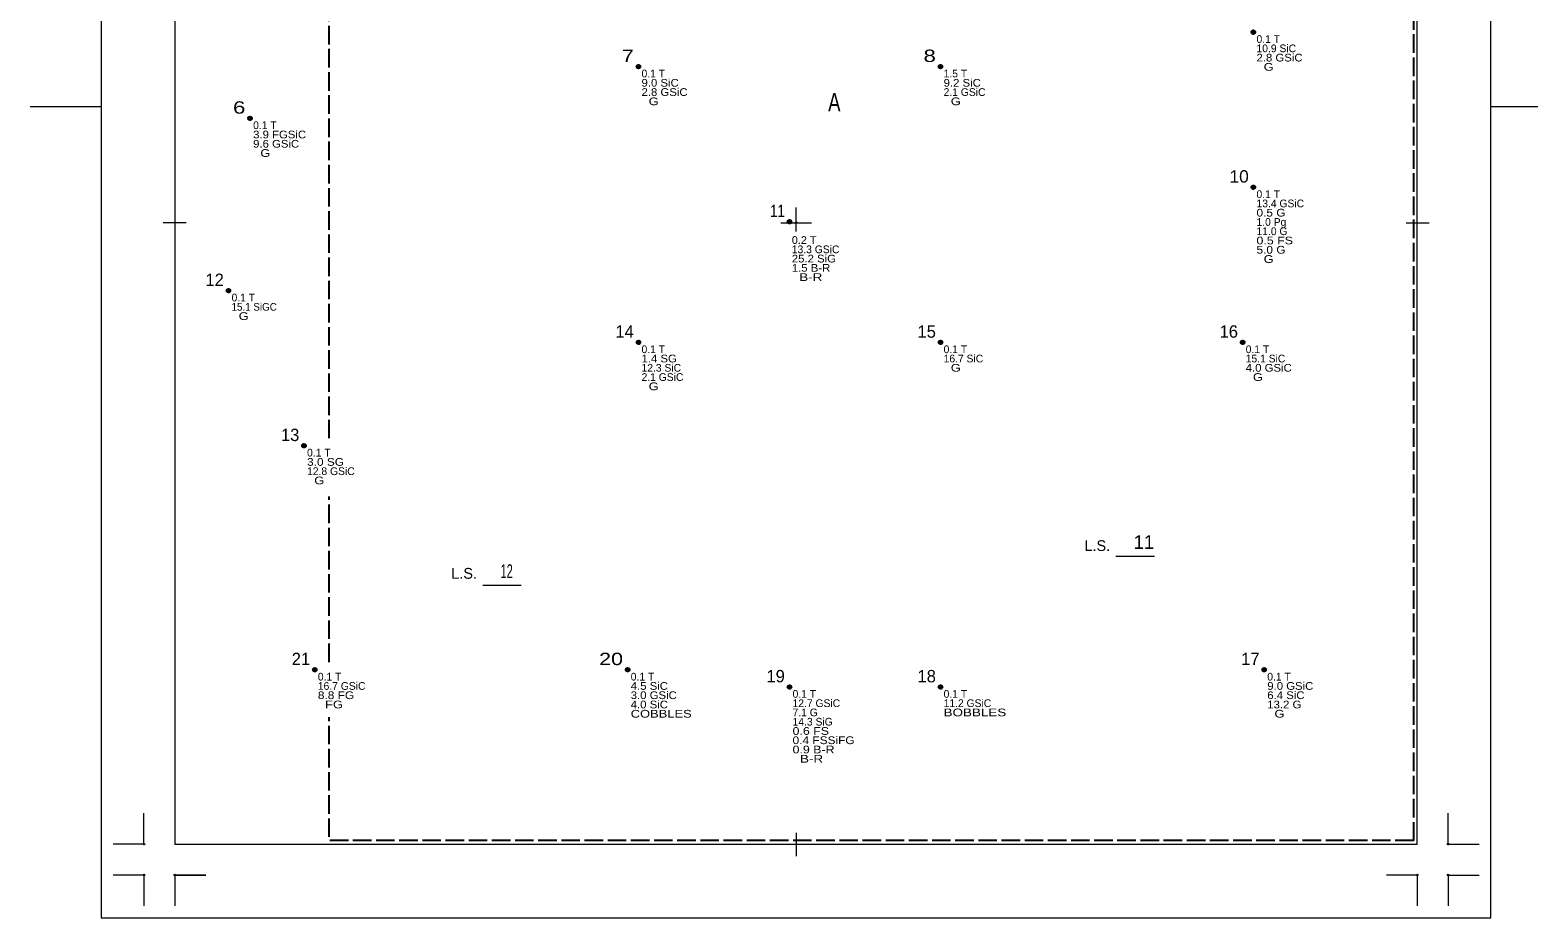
# Model space of a CAD drawing. Extents: x -496 to 480, y -450 to 700.
# Drawn here: x -496 to 480, y -450 to 125 of the extents above; entities that cross this region are included whole.
import ezdxf
from ezdxf.enums import TextEntityAlignment as Align

# ---------------------------------------------------------------- set-up
doc = ezdxf.new("R2010")
doc.units = 0
doc.header["$LTSCALE"] = 2
doc.header["$PDMODE"] = 32
doc.header["$PDSIZE"] = 1
doc.linetypes.add('LONG_DASHED', pattern=[7.5, 6, -1.5])
doc.layers.add('1', color=7, linetype='Continuous', lineweight=13)
doc.layers.add('2', color=7, linetype='Continuous', lineweight=35)

msp = doc.modelspace()

# ---------------------------------------------------------------- linework, layer by layer
at = {"layer": '1'}
for p, q in [((-402.391, 402.339), (-402.391, -402.333)), ((-450.017, 74.973), (-496.057, 74.973)), ((480.331, 74.973), (449.983, 74.973)), ((-0.017, -5.706), (-0.017, 9.973)), ((-395.017, -0.027), (-410.017, -0.027)), ((-10.017, -0.027), (9.983, -0.027)), ((394.983, -0.027), (409.983, -0.027)), ((207.114, -215.907), (232.114, -215.907)), ((-202.998, -234.618), (-177.998, -234.618)), ((-422.391, -402.333), (-422.391, -382.333)), ((422.281, -402.333), (422.281, -382.333)), ((-0.017, -395.027), (-0.017, -410.027)), ((-422.391, -402.333), (-442.391, -402.333)), ((-402.391, -402.333), (402.281, -402.333)), ((422.281, -402.333), (442.281, -402.333)), ((-422.391, -422.333), (-442.391, -422.333)), ((-422.391, -422.333), (-422.391, -442.333)), ((-402.391, -422.333), (-402.391, -442.333)), ((402.281, -422.333), (382.281, -422.333)), ((402.281, -422.333), (402.281, -442.333)), ((422.281, -422.333), (422.281, -442.333)), ((422.281, -422.333), (442.281, -422.333)), ((-450.017, -450.027), (449.983, -450.027))]:
    msp.add_line(p, q, dxfattribs=at)
for points in [[(449.983, -450.027), (449.983, 399.973), (449.983, 699.973), (-450.017, 699.973), (-450.017, 49.973), (-450.017, -450.027)], [(402.281, -402.333), (402.281, 402.339), (-402.391, 402.339)], [(-402.391, -422.333), (-382.391, -422.333), (-402.391, -422.333)]]:
    msp.add_lwpolyline(points, dxfattribs=at)
for p in [(0, 0), (0.001, -0.011), (-422.391, -402.333), (422.281, -402.333), (-422.391, -422.333), (-402.391, -422.333), (402.281, -422.333), (422.281, -422.333)]:
    msp.add_point(p, dxfattribs=at)
at = {"layer": '2', "linetype": 'LONG_DASHED', "lineweight": 25}
for p, q in [((-302.391, -139.499), (-302.391, 402.339)), ((-302.391, -284.427), (-302.391, -177.191)), ((-302.391, -397.661), (-302.391, -320.02)), ((400, -400), (-302.391, -400))]:
    msp.add_line(p, q, dxfattribs=at)
msp.add_lwpolyline([(400, -400), (400, 400), (-302.391, 400)], dxfattribs=at)
at = {"layer": '2'}
for centre in [(296.124, 123.414), (-102.135, 101.1), (93.501, 101.1), (-353.667, 67.629), (296.124, 23.001), (-4.317, 0.687), (-367.641, -43.941), (-102.135, -77.412), (93.501, -77.412), (289.137, -77.412), (-318.732, -144.354), (-311.745, -289.395), (-109.122, -289.395), (303.111, -289.395), (-4.317, -300.552), (93.501, -300.552)]:
    msp.add_circle(centre, 1, dxfattribs=at)
for points in [[(296.113, 124.301), (296.843, 123.897), (296.995, 123.048), (296.31, 122.52), (295.501, 122.751), (295.214, 123.509), (295.461, 124.071), (296.034, 124.239), (296.708, 123.745), (296.692, 123.003), (296.175, 122.745), (295.652, 122.914), (295.428, 123.56), (296.012, 124.026), (296.45, 123.492), (296.411, 123.009), (295.782, 123.144), (295.928, 123.779), (296.22, 123.228)], [(-102.146, 101.987), (-101.416, 101.583), (-101.264, 100.734), (-101.949, 100.206), (-102.758, 100.437), (-103.045, 101.195), (-102.798, 101.757), (-102.225, 101.925), (-101.551, 101.431), (-101.567, 100.689), (-102.084, 100.431), (-102.607, 100.6), (-102.831, 101.246), (-102.247, 101.712), (-101.809, 101.178), (-101.848, 100.695), (-102.477, 100.83), (-102.331, 101.465), (-102.039, 100.914)], [(93.49, 101.987), (94.22, 101.583), (94.372, 100.734), (93.687, 100.206), (92.878, 100.437), (92.591, 101.195), (92.838, 101.757), (93.411, 101.925), (94.085, 101.431), (94.069, 100.689), (93.552, 100.431), (93.029, 100.6), (92.805, 101.246), (93.389, 101.712), (93.827, 101.178), (93.788, 100.695), (93.159, 100.83), (93.305, 101.465), (93.597, 100.914)], [(-353.678, 68.516), (-352.948, 68.112), (-352.796, 67.263), (-353.481, 66.735), (-354.29, 66.966), (-354.577, 67.724), (-354.33, 68.286), (-353.757, 68.454), (-353.083, 67.96), (-353.099, 67.218), (-353.616, 66.96), (-354.139, 67.129), (-354.363, 67.775), (-353.779, 68.241), (-353.341, 67.707), (-353.38, 67.224), (-354.009, 67.359), (-353.863, 67.994), (-353.571, 67.443)], [(296.113, 23.888), (296.843, 23.484), (296.995, 22.635), (296.31, 22.107), (295.501, 22.338), (295.214, 23.096), (295.461, 23.658), (296.034, 23.826), (296.708, 23.332), (296.692, 22.59), (296.175, 22.332), (295.652, 22.501), (295.428, 23.147), (296.012, 23.613), (296.45, 23.079), (296.411, 22.596), (295.782, 22.731), (295.928, 23.366), (296.22, 22.815)], [(-4.328, 1.574), (-3.598, 1.17), (-3.446, 0.321), (-4.131, -0.207), (-4.94, 0.024), (-5.227, 0.782), (-4.98, 1.344), (-4.407, 1.512), (-3.733, 1.018), (-3.749, 0.276), (-4.266, 0.018), (-4.789, 0.187), (-5.013, 0.833), (-4.429, 1.299), (-3.991, 0.765), (-4.03, 0.282), (-4.659, 0.417), (-4.513, 1.052), (-4.221, 0.501)], [(-367.652, -43.054), (-366.922, -43.458), (-366.77, -44.307), (-367.455, -44.835), (-368.264, -44.604), (-368.551, -43.846), (-368.304, -43.284), (-367.731, -43.116), (-367.057, -43.61), (-367.073, -44.352), (-367.59, -44.61), (-368.113, -44.441), (-368.337, -43.795), (-367.753, -43.329), (-367.315, -43.863), (-367.354, -44.346), (-367.983, -44.211), (-367.837, -43.576), (-367.545, -44.127)], [(-102.146, -76.525), (-101.416, -76.929), (-101.264, -77.778), (-101.949, -78.306), (-102.758, -78.075), (-103.045, -77.317), (-102.798, -76.755), (-102.225, -76.587), (-101.551, -77.081), (-101.567, -77.823), (-102.084, -78.081), (-102.607, -77.912), (-102.831, -77.266), (-102.247, -76.8), (-101.809, -77.334), (-101.848, -77.817), (-102.477, -77.682), (-102.331, -77.047), (-102.039, -77.598)], [(93.49, -76.525), (94.22, -76.929), (94.372, -77.778), (93.687, -78.306), (92.878, -78.075), (92.591, -77.317), (92.838, -76.755), (93.411, -76.587), (94.085, -77.081), (94.069, -77.823), (93.552, -78.081), (93.029, -77.912), (92.805, -77.266), (93.389, -76.8), (93.827, -77.334), (93.788, -77.817), (93.159, -77.682), (93.305, -77.047), (93.597, -77.598)], [(289.126, -76.525), (289.856, -76.929), (290.008, -77.778), (289.323, -78.306), (288.514, -78.075), (288.227, -77.317), (288.474, -76.755), (289.047, -76.587), (289.721, -77.081), (289.705, -77.823), (289.188, -78.081), (288.665, -77.912), (288.441, -77.266), (289.025, -76.8), (289.463, -77.334), (289.424, -77.817), (288.795, -77.682), (288.941, -77.047), (289.233, -77.598)], [(-318.743, -143.467), (-318.013, -143.871), (-317.861, -144.72), (-318.546, -145.248), (-319.355, -145.017), (-319.642, -144.259), (-319.395, -143.697), (-318.822, -143.529), (-318.148, -144.023), (-318.164, -144.765), (-318.681, -145.023), (-319.204, -144.854), (-319.428, -144.208), (-318.844, -143.742), (-318.406, -144.276), (-318.445, -144.759), (-319.074, -144.624), (-318.928, -143.989), (-318.636, -144.54)], [(-311.756, -288.508), (-311.026, -288.912), (-310.874, -289.761), (-311.559, -290.289), (-312.368, -290.058), (-312.655, -289.3), (-312.408, -288.738), (-311.835, -288.57), (-311.161, -289.064), (-311.177, -289.806), (-311.694, -290.064), (-312.217, -289.895), (-312.441, -289.249), (-311.857, -288.783), (-311.419, -289.317), (-311.458, -289.8), (-312.087, -289.665), (-311.941, -289.03), (-311.649, -289.581)], [(-109.133, -288.508), (-108.403, -288.912), (-108.251, -289.761), (-108.936, -290.289), (-109.745, -290.058), (-110.032, -289.3), (-109.785, -288.738), (-109.212, -288.57), (-108.538, -289.064), (-108.554, -289.806), (-109.071, -290.064), (-109.594, -289.895), (-109.818, -289.249), (-109.234, -288.783), (-108.796, -289.317), (-108.835, -289.8), (-109.464, -289.665), (-109.318, -289.03), (-109.026, -289.581)], [(303.1, -288.508), (303.83, -288.912), (303.982, -289.761), (303.297, -290.289), (302.488, -290.058), (302.201, -289.3), (302.448, -288.738), (303.021, -288.57), (303.695, -289.064), (303.679, -289.806), (303.162, -290.064), (302.639, -289.895), (302.415, -289.249), (302.999, -288.783), (303.437, -289.317), (303.398, -289.8), (302.769, -289.665), (302.915, -289.03), (303.207, -289.581)], [(-4.328, -299.665), (-3.598, -300.069), (-3.446, -300.918), (-4.131, -301.446), (-4.94, -301.215), (-5.227, -300.457), (-4.98, -299.895), (-4.407, -299.727), (-3.733, -300.221), (-3.749, -300.963), (-4.266, -301.221), (-4.789, -301.052), (-5.013, -300.406), (-4.429, -299.94), (-3.991, -300.474), (-4.03, -300.957), (-4.659, -300.822), (-4.513, -300.187), (-4.221, -300.738)], [(93.49, -299.665), (94.22, -300.069), (94.372, -300.918), (93.687, -301.446), (92.878, -301.215), (92.591, -300.457), (92.838, -299.895), (93.411, -299.727), (94.085, -300.221), (94.069, -300.963), (93.552, -301.221), (93.029, -301.052), (92.805, -300.406), (93.389, -299.94), (93.827, -300.474), (93.788, -300.957), (93.159, -300.822), (93.305, -300.187), (93.597, -300.738)]]:
    msp.add_spline(points, degree=3, dxfattribs=at)

# ---------------------------------------------------------------- texts
at = {"layer": '1'}
for s, height, p in [('11', 8.89, (225.202, -211.189)), ('L.S.', 7, (195.033, -212.53)), ('L.S.', 7, (-215.009, -230.48))]:
    msp.add_text(s, height=height, dxfattribs=at).set_placement(p, align=Align.CENTER)
at = {"layer": '1', "width": 0.6}
msp.add_text('12', height=8.89, dxfattribs=at).set_placement((-187.46, -230.008), align=Align.CENTER)
at = {"layer": '2'}
for s, p in [('0.1 T      ', (298.124, 116.414)), ('10.9 SiC   ', (298.124, 110.414)), ('0.1 T      ', (-100.135, 94.1)), ('1.5 T      ', (95.501, 94.1)), ('2.1 GSiC   ', (95.501, 82.1)), ('0.1 T      ', (-351.667, 60.629)), ('0.1 T      ', (298.124, 16.001)), ('13.4 GSiC  ', (298.124, 10.001)), ('1.0 Pg     ', (298.124, -1.999)), ('11.0 G     ', (298.124, -7.999)), ('13.3 GSiC  ', (-2.811, -19.71)), ('0.1 T      ', (-365.641, -50.941)), ('0.1 T      ', (-100.135, -84.412)), ('0.1 T      ', (95.501, -84.412)), ('16.7 SiC   ', (95.501, -90.412)), ('0.1 T      ', (291.137, -84.412)), ('15.1 SiC   ', (291.137, -90.412)), ('2.1 GSiC   ', (-100.135, -102.412)), ('12.3 SiC   ', (-100.135, -96.412)), ('0.1 T      ', (-316.732, -151.354)), ('12.8 GSiC  ', (-316.732, -163.354)), ('0.1 T      ', (-309.745, -296.395)), ('0.1 T      ', (-107.122, -296.395)), ('0.1 T      ', (305.111, -296.395)), ('16.7 GSiC  ', (-309.745, -302.395)), ('0.1 T      ', (-2.317, -307.552)), ('0.1 T      ', (95.501, -307.552)), ('12.7 GSiC  ', (-2.317, -313.552)), ('11.2 GSiC  ', (95.501, -313.552)), ('7.1 G      ', (-2.317, -319.552)), ('14.3 SiG   ', (-2.317, -325.552))]:
    msp.add_text(s, height=5, dxfattribs=at).set_placement(p)
for s, width, p in [('  7', 1.3, (-105.136, 104.1)), ('  8', 1.35, (90.5, 104.1)), ('  6', 1.35, (-356.668, 70.629)), (' 10', 1.05, (293.123, 26.001)), (' 11', 0.8, (-7.318, 3.687)), (' 20', 1.3, (-112.123, -286.395))]:
    msp.add_text(s, height=8, dxfattribs=dict(at, width=width)).set_placement(p, align=Align.RIGHT)
for s, width, p in [('2.8 GSiC   ', 1.1, (298.124, 104.414)), ('  G        ', 1.25, (298.124, 98.414)), ('9.0 SiC    ', 1.1, (-100.135, 88.1)), ('9.2 SiC    ', 1.1, (95.501, 88.1)), ('2.8 GSiC   ', 1.1, (-100.135, 82.1)), ('  G        ', 1.25, (-100.135, 76.1)), ('  G        ', 1.25, (95.501, 76.1)), ('3.9 FGSiC  ', 1.1, (-351.667, 54.629)), ('9.6 GSiC   ', 1.1, (-351.667, 48.629)), ('  G        ', 1.25, (-351.667, 42.629)), ('0.5 G      ', 1.15, (298.124, 4.001)), ('0.2 T      ', 1.05, (-2.811, -13.71)), ('0.5 FS     ', 1.2, (298.124, -13.999)), ('5.0 G      ', 1.15, (298.124, -19.999)), ('25.2 SiG   ', 1.1, (-2.811, -25.71)), ('1.5 B-R    ', 1.1, (-2.811, -31.71)), ('  G        ', 1.25, (298.124, -25.999)), ('  B-R      ', 1.3, (-2.811, -37.71)), ('15.1 SiGC  ', 0.95, (-365.641, -56.941)), ('  G        ', 1.25, (-365.641, -62.941)), ('1.4 SG     ', 1.1, (-100.135, -90.412)), ('  G        ', 1.25, (95.501, -96.412)), ('4.0 GSiC   ', 1.1, (291.137, -96.412)), ('  G        ', 1.25, (291.137, -102.412)), ('  G        ', 1.25, (-100.135, -108.412)), ('3.0 SG     ', 1.15, (-316.732, -157.354)), ('  G        ', 1.25, (-316.732, -169.354)), ('4.5 SiC    ', 1.1, (-107.122, -302.395)), ('9.0 GSiC   ', 1.1, (305.111, -302.395)), ('8.8 FG     ', 1.15, (-309.745, -308.395)), ('  FG       ', 1.25, (-309.745, -314.395)), ('4.0 SiC    ', 1.1, (-107.122, -314.395)), ('3.0 GSiC   ', 1.1, (-107.122, -308.395)), ('6.4 SiC    ', 1.1, (305.111, -308.395)), ('13.2 G     ', 1.1, (305.111, -314.395)), ('COBBLES    ', 1.25, (-107.122, -320.395)), ('BOBBLES    ', 1.3, (95.501, -319.552)), ('  G        ', 1.25, (305.111, -320.395)), ('0.6 FS     ', 1.2, (-2.317, -331.552)), ('0.4 FSSiFG ', 1.15, (-2.317, -337.552)), ('0.9 B-R    ', 1.2, (-2.317, -343.552)), ('  B-R      ', 1.3, (-2.317, -349.552))]:
    msp.add_text(s, height=5, dxfattribs=dict(at, width=width)).set_placement(p)
at = {"layer": '2', "width": 0.75}
msp.add_text('A', height=12, dxfattribs=at).set_placement((24.728, 72.103), align=Align.CENTER)
at = {"layer": '2'}
for s, p in [(' 12', (-370.642, -40.941)), (' 14', (-105.136, -74.412)), (' 15', (90.5, -74.412)), (' 16', (286.136, -74.412)), (' 13', (-321.733, -141.354)), (' 21', (-314.746, -286.395)), (' 17', (300.11, -286.395)), (' 19', (-7.318, -297.552)), (' 18', (90.5, -297.552))]:
    msp.add_text(s, height=8, dxfattribs=at).set_placement(p, align=Align.RIGHT)

doc.saveas('drawing.dxf')
